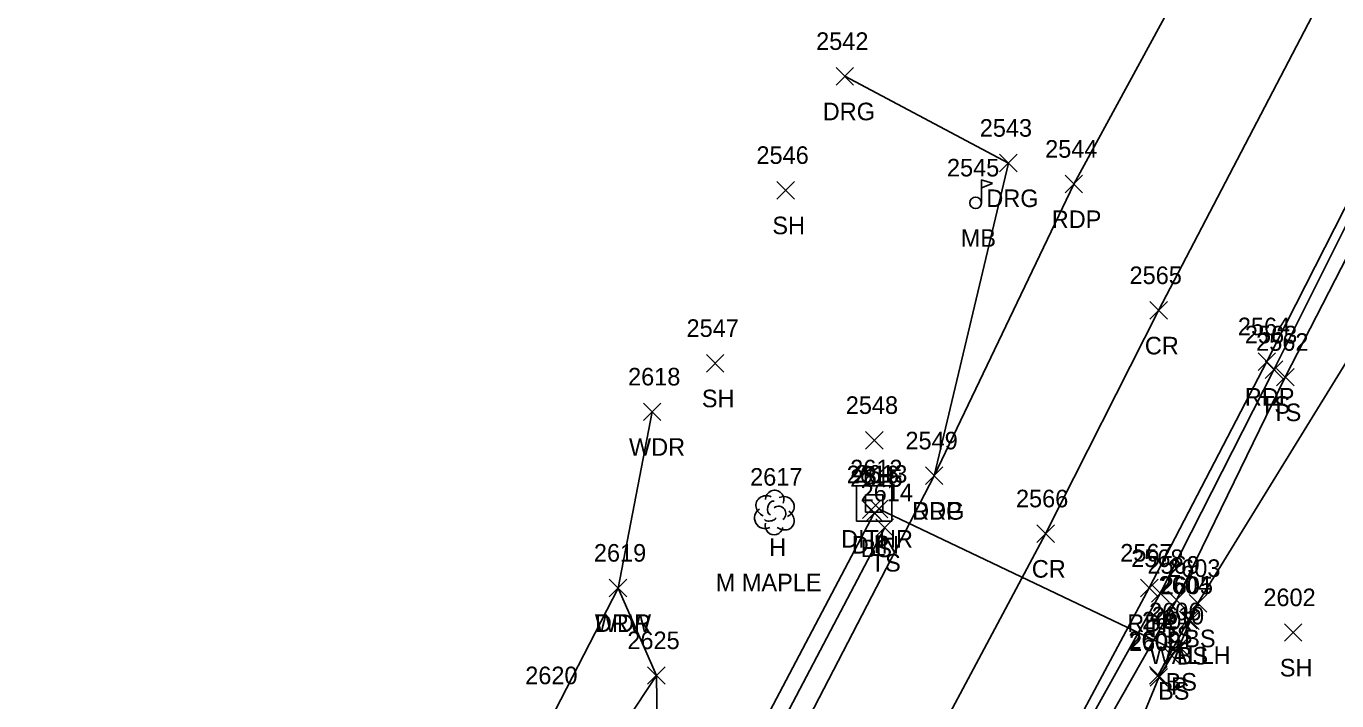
# Model space of a CAD drawing. Extents: x 1678863 to 1683592, y 407783 to 418211.
# Drawn here: x 1680535.7 to 1680684.8, y 415624 to 415700.7 of the extents above; entities that cross this region are included whole.
import ezdxf

# ---------------------------------------------------------------- set-up
doc = ezdxf.new("R2010")
doc.units = 0
for name, color, linetype in [('D_A', 7, 'Continuous'), ('D_I', 7, 'Continuous'), ('D_TIC', 7, 'Continuous'), ('DCP', 7, 'Continuous'), ('DHW', 7, 'Continuous'), ('DS', 7, 'Continuous'), ('L_A', 7, 'Continuous'), ('L_C', 7, 'Continuous'), ('L_I', 7, 'Continuous'), ('L_TIC', 7, 'Continuous'), ('LAWA', 7, 'Continuous'), ('LELB', 7, 'Continuous'), ('LMB', 7, 'Continuous'), ('LTD', 7, 'Continuous'), ('P_A', 7, 'Continuous'), ('P_I', 7, 'Continuous'), ('P_TIC', 7, 'Continuous'), ('PET', 7, 'Continuous'), ('PRC', 7, 'Continuous'), ('R_A', 7, 'Continuous'), ('R_I', 7, 'Continuous'), ('R_TIC', 7, 'Continuous'), ('RDG', 7, 'Continuous'), ('RDW', 7, 'Continuous')]:
    doc.layers.add(name, color=color, linetype=linetype)

msp = doc.modelspace()

# ---------------------------------------------------------------- linework, layer by layer
at = {"layer": 'D_TIC'}
for points in [[(1680630.83, 415644.77), (1680632.83, 415646.77)], [(1680632.83, 415644.77), (1680630.83, 415646.77)], [(1680631.72, 415644.83), (1680633.72, 415646.83)], [(1680633.72, 415644.83), (1680631.72, 415646.83)], [(1680666.89, 415632.2), (1680668.89, 415634.2)], [(1680668.89, 415632.2), (1680666.89, 415634.2)], [(1680665.55, 415628.71), (1680667.55, 415630.71)], [(1680667.55, 415628.71), (1680665.55, 415630.71)], [(1680663.46, 415625.93), (1680665.46, 415627.93)], [(1680665.46, 415625.93), (1680663.46, 415627.93)]]:
    msp.add_lwpolyline(points, dxfattribs=at)
at = {"layer": 'DCP'}
msp.add_lwpolyline([(1680666.55, 415629.71), (1680632.72, 415645.83)], dxfattribs=at)
at = {"layer": 'DHW'}
msp.add_lwpolyline([(1680667.89, 415633.2), (1680664.46, 415626.93)], dxfattribs=at)
at = {"layer": 'DS'}
for p, q in [((1680630.15, 415648.46), (1680634.15, 415648.46)), ((1680630.15, 415644.46), (1680630.16, 415648.46)), ((1680631.15, 415647.46), (1680633.15, 415647.46)), ((1680631.15, 415645.46), (1680631.15, 415647.46)), ((1680633.15, 415647.46), (1680633.15, 415645.46)), ((1680634.15, 415648.46), (1680634.15, 415644.46)), ((1680632.15, 415646.47), (1680632.15, 415646.47)), ((1680633.15, 415645.46), (1680631.15, 415645.46)), ((1680634.15, 415644.46), (1680630.15, 415644.46)), ((1680632.65, 415644.46), (1680633.15, 415644.46))]:
    msp.add_line(p, q, dxfattribs=at)
at = {"layer": 'L_TIC'}
for points in [[(1680621.08, 415681.09), (1680623.08, 415683.09)], [(1680623.08, 415681.09), (1680621.08, 415683.09)], [(1680613.07, 415661.41), (1680615.07, 415663.41)], [(1680615.07, 415661.41), (1680613.07, 415663.41)], [(1680676.63, 415660.68), (1680678.63, 415662.68)], [(1680678.63, 415660.68), (1680676.63, 415662.68)], [(1680677.91, 415659.83), (1680679.91, 415661.83)], [(1680679.91, 415659.83), (1680677.91, 415661.83)], [(1680605.9, 415655.89), (1680607.9, 415657.89)], [(1680607.9, 415655.89), (1680605.9, 415657.89)], [(1680631.18, 415652.65), (1680633.18, 415654.65)], [(1680633.18, 415652.65), (1680631.18, 415654.65)], [(1680631.17, 415644.36), (1680633.17, 415646.36)], [(1680633.17, 415644.36), (1680631.17, 415646.36)], [(1680632.35, 415642.72), (1680634.35, 415644.72)], [(1680634.35, 415642.72), (1680632.35, 415644.72)], [(1680602.02, 415635.85), (1680604.02, 415637.85)], [(1680604.02, 415635.85), (1680602.02, 415637.85)], [(1680663.7, 415635.24), (1680665.7, 415637.24)], [(1680665.7, 415635.24), (1680663.7, 415637.24)], [(1680665.54, 415634.48), (1680667.54, 415636.48)], [(1680667.54, 415634.48), (1680665.54, 415636.48)], [(1680667.98, 415634.11), (1680669.98, 415636.11)], [(1680669.98, 415634.11), (1680667.98, 415636.11)], [(1680667.13, 415632.15), (1680669.13, 415634.15)], [(1680669.13, 415632.15), (1680667.13, 415634.15)], [(1680678.81, 415630.79), (1680680.81, 415632.79)], [(1680680.81, 415630.79), (1680678.81, 415632.79)], [(1680665.86, 415629.18), (1680667.86, 415631.18)], [(1680667.86, 415629.18), (1680665.86, 415631.18)], [(1680665.01, 415628.15), (1680667.01, 415630.15)], [(1680667.01, 415628.15), (1680665.01, 415630.15)], [(1680606.38, 415625.9), (1680608.38, 415627.9)], [(1680608.38, 415625.9), (1680606.38, 415627.9)], [(1680663.53, 415625.69), (1680665.53, 415627.69)], [(1680665.53, 415625.69), (1680663.53, 415627.69)]]:
    msp.add_lwpolyline(points, dxfattribs=at)
at = {"layer": 'LAWA'}
msp.add_lwpolyline([(1680606.9, 415656.89), (1680603.02, 415636.85), (1680607.38, 415626.9), (1680607.52, 415618.11), (1680596.78, 415583.99), (1680577.19, 415543.55), (1680564.61, 415514.54), (1680555.67, 415493.69), (1680550.62, 415482.36), (1680543.43, 415462.07), (1680536.67, 415456.94)], dxfattribs=at)
at = {"layer": 'LELB'}
for points in [[(1680779.02, 415827.07), (1680764.6, 415800.72), (1680749.76, 415782.11), (1680734.08, 415752.62), (1680721.13, 415730.53), (1680704.81, 415692.99), (1680704.75, 415688.18), (1680689.04, 415667.71), (1680668.98, 415635.11), (1680668.13, 415633.15), (1680666.86, 415630.18), (1680666.01, 415629.15), (1680664.53, 415626.69), (1680656.16, 415606.33), (1680642.64, 415571.64), (1680625.84, 415544.48), (1680606.01, 415498.25), (1680595.98, 415466.06), (1680584.22, 415440)], [(1680760.46, 415817.8), (1680759.2, 415806.58), (1680737.44, 415772.53), (1680718.55, 415734.23), (1680698.03, 415698.1), (1680678.91, 415660.83), (1680666.54, 415635.48), (1680651.21, 415608.56), (1680637.64, 415579.7), (1680620.72, 415545.75), (1680603.88, 415511.3), (1680588.55, 415474.85)], [(1680716.45, 415735.15), (1680696.34, 415699.12), (1680677.63, 415661.68), (1680664.7, 415636.24), (1680649.94, 415609.72), (1680635.85, 415580.47), (1680619.12, 415546.83), (1680602.77, 415511.81), (1680588.55, 415474.85)], [(1680632.17, 415645.36), (1680615.45, 415613.7), (1680599.55, 415582.66), (1680582, 415541.28), (1680567.86, 415513.08), (1680554.53, 415480.69), (1680546.59, 415460.78), (1680542.6, 415453.6), (1680540.64, 415455.07)], [(1680633.35, 415643.72), (1680617.1, 415612.79), (1680602.64, 415581.48), (1680583.69, 415540.74), (1680570.36, 415512.19), (1680555.93, 415479.46), (1680544.79, 415450.21), (1680534.43, 415426.53), (1680521.07, 415388.59), (1680509.57, 415354.33), (1680496.9, 415318.18), (1680492.8, 415319.1)]]:
    msp.add_lwpolyline(points, dxfattribs=at)
at = {"layer": 'LMB'}
for p, q in [((1680644.34, 415683.26), (1680645.63, 415682.88)), ((1680644.35, 415680.67), (1680644.35, 415683.26)), ((1680644.35, 415682.36), (1680645.63, 415682.87)), ((1680643.69, 415680.66), (1680643.69, 415680.66))]:
    msp.add_line(p, q, dxfattribs=at)
msp.add_circle((1680643.69, 415680.66), 0.656, dxfattribs=at)
at = {"layer": 'LTD'}
msp.add_line((1680620.78, 415645.49), (1680620.78, 415645.49), dxfattribs=at)
msp.add_line((1680620.78, 415645.49), (1680620.78, 415645.49), dxfattribs=at)
msp.add_arc((1680620.83, 415646.92), 1.05, 335.5272, 180.9563, dxfattribs=at)
for centre, major_axis, ratio, start_param, end_param in [((1680619.99, 415646.15), (1.21, -0.51), 0.895232, 1.570796, 4.712389), ((1680620.57, 415645.95), (-0.208, -0.792), 0.645439, 3.141593, 6.283185), ((1680621.28, 415645.32), (-0.5, 0.667), 0.989748, 3.141593, 6.283185), ((1680621.82, 415646.07), (-1.14, -0.48), 0.949671, 1.570796, 4.712389), ((1680619.7, 415644.78), (0.58, -1.04), 0.959034, 3.141593, 6.283185), ((1680620.32, 415644.74), (-0.625, -0.083), 0.423636, 0, 3.141593), ((1680621.78, 415644.66), (-1.09, 0.79), 0.841452, 1.570796, 4.712389), ((1680620.78, 415643.99), (0.26, 1.06), 0.942809, 1.570796, 4.712389)]:
    msp.add_ellipse(centre, major_axis=major_axis, ratio=ratio, start_param=start_param, end_param=end_param, dxfattribs=at)
at = {"layer": 'P_TIC'}
for points in [[(1680653.86, 415681.79), (1680655.86, 415683.79)], [(1680655.86, 415681.79), (1680653.86, 415683.79)], [(1680663.5, 415667.42), (1680665.5, 415669.42)], [(1680665.5, 415667.42), (1680663.5, 415669.42)], [(1680675.82, 415661.6), (1680677.82, 415663.6)], [(1680677.82, 415661.6), (1680675.82, 415663.6)], [(1680637.98, 415648.62), (1680639.98, 415650.62)], [(1680639.98, 415648.62), (1680637.98, 415650.62)], [(1680650.65, 415642.03), (1680652.65, 415644.03)], [(1680652.65, 415642.03), (1680650.65, 415644.03)], [(1680662.45, 415635.86), (1680664.45, 415637.86)], [(1680664.45, 415635.86), (1680662.45, 415637.86)]]:
    msp.add_lwpolyline(points, dxfattribs=at)
at = {"layer": 'PET'}
for points in [[(1680714.62, 415736.11), (1680695.56, 415699.43), (1680676.82, 415662.6), (1680663.45, 415636.86), (1680649.23, 415610.25), (1680634.13, 415580.72), (1680618.24, 415547.61), (1680602.16, 415512.05), (1680586.29, 415476.01), (1680574.61, 415447.7), (1680563.89, 415420.31), (1680552.33, 415389.01), (1680543.5, 415364.71), (1680535.14, 415340.61), (1680523.39, 415305.41), (1680517.77, 415286.76), (1680506.72, 415249.99), (1680495.8, 415211.55), (1680487.74, 415180.8)], [(1680674.8, 415719.5), (1680654.86, 415682.79), (1680638.98, 415649.62), (1680619.32, 415611.68), (1680604.15, 415580.83), (1680584.73, 415539.97), (1680571.82, 415511.9), (1680557.49, 415478.39), (1680544.08, 415445.87), (1680536.29, 415425.79), (1680523.06, 415388.11), (1680510.43, 415353.62), (1680497.85, 415315.66), (1680486.4, 415279.22), (1680483.29, 415266.82), (1680478.84, 415252.28), (1680468.22, 415214.69), (1680459.71, 415182.46)]]:
    msp.add_lwpolyline(points, dxfattribs=at)
at = {"layer": 'PRC'}
msp.add_lwpolyline([(1680684.22, 415706.23), (1680664.5, 415668.42), (1680651.65, 415643.03), (1680631.65, 415605.57), (1680617, 415575.83), (1680596.48, 415533.87), (1680584.46, 415507.14), (1680569.15, 415472.46), (1680556.96, 415440.74), (1680549.08, 415420.65), (1680536.22, 415384.73), (1680523.38, 415348.31), (1680512.19, 415314.3), (1680500.03, 415274.9), (1680490.66, 415243.58), (1680481.59, 415211.17), (1680473.06, 415178.67)], dxfattribs=at)
at = {"layer": 'R_TIC'}
for points in [[(1680627.81, 415694.05), (1680629.81, 415696.05)], [(1680629.81, 415694.05), (1680627.81, 415696.05)], [(1680646.42, 415684.18), (1680648.42, 415686.18)], [(1680648.42, 415684.18), (1680646.42, 415686.18)], [(1680637.98, 415648.62), (1680639.98, 415650.62)], [(1680639.98, 415648.62), (1680637.98, 415650.62)], [(1680602.02, 415635.85), (1680604.02, 415637.85)], [(1680604.02, 415635.85), (1680602.02, 415637.85)], [(1680606.38, 415625.9), (1680608.38, 415627.9)], [(1680608.38, 415625.9), (1680606.38, 415627.9)]]:
    msp.add_lwpolyline(points, dxfattribs=at)
at = {"layer": 'RDG'}
msp.add_lwpolyline([(1680628.81, 415695.05), (1680647.42, 415685.18), (1680638.98, 415649.62)], dxfattribs=at)
at = {"layer": 'RDW'}
for points in [[(1680603.02, 415636.85), (1680595.85, 415622.91), (1680580.1, 415606.3)], [(1680579.57, 415593.72), (1680597.2, 415611.55), (1680607.38, 415626.9)]]:
    msp.add_lwpolyline(points, dxfattribs=at)

# ---------------------------------------------------------------- texts
at = {"layer": 'D_A'}
for s, p in [('DITHR', (1680628.39, 415641.44)), ('DIIN', (1680629.6, 415640.77)), ('P', (1680632.1, 415640.83)), ('WALLH', (1680663.48, 415628.2)), ('P', (1680665.93, 415624.71))]:
    msp.add_text(s, height=2, dxfattribs=at).set_placement(p)
at = {"layer": 'D_I'}
for s, p in [('2616', (1680629.03, 415648.77)), ('2612', (1680629.42, 415649.44)), ('2613', (1680629.98, 415648.83)), ('2604', (1680664.5, 415636.2)), ('2610', (1680663.73, 415632.71)), ('2609', (1680661.07, 415629.93))]:
    msp.add_text(s, height=2, dxfattribs=at).set_placement(p)
at = {"layer": 'L_A'}
for s, p in [('SH', (1680620.57, 415677.09)), ('MB', (1680642, 415675.66)), ('SH', (1680612.55, 415657.41)), ('TS', (1680676.04, 415656.68)), ('TS', (1680677.32, 415655.83)), ('WDR', (1680604.26, 415651.89)), ('SH', (1680630.67, 415648.65)), ('H', (1680620.21, 415640.49)), ('BS', (1680630.61, 415640.36)), ('TS', (1680631.76, 415638.72)), ('WDR', (1680600.38, 415631.85)), ('TS', (1680663.11, 415631.24)), ('TS', (1680664.95, 415630.48)), ('BS', (1680667.42, 415630.11)), ('BS', (1680666.57, 415628.15)), ('SH', (1680678.29, 415626.79)), ('BS', (1680665.3, 415625.18)), ('BS', (1680664.45, 415624.15))]:
    msp.add_text(s, height=2, dxfattribs=at).set_placement(p)
at = {"layer": 'L_C'}
msp.add_text('M MAPLE', height=2, dxfattribs=at).set_placement((1680614.13, 415636.49))
at = {"layer": 'L_I'}
for s, p in [('2546', (1680618.76, 415685.09)), ('2545', (1680640.43, 415683.66)), ('2547', (1680610.81, 415665.41)), ('2563', (1680674.32, 415664.68)), ('2562', (1680675.6, 415663.83)), ('2618', (1680604.16, 415659.89)), ('2548', (1680628.92, 415656.65)), ('2617', (1680618.04, 415648.49)), ('2615', (1680629.43, 415648.36)), ('2614', (1680630.61, 415646.72)), ('2619', (1680600.27, 415639.85)), ('2568', (1680661.39, 415639.24)), ('2569', (1680663.23, 415638.48)), ('2603', (1680665.59, 415638.11)), ('2605', (1680664.74, 415636.15)), ('2602', (1680676.42, 415634.79)), ('2607', (1680662.62, 415632.15)), ('2606', (1680663.42, 415633.18)), ('2625', (1680604.08, 415629.9)), ('2608', (1680661.14, 415629.69))]:
    msp.add_text(s, height=2, dxfattribs=at).set_placement(p)
at = {"layer": 'P_A'}
for s, p in [('RDP', (1680652.35, 415677.79)), ('CR', (1680662.94, 415663.42)), ('RDP', (1680674.31, 415657.6)), ('RDP', (1680636.47, 415644.62)), ('CR', (1680650.08, 415638.03)), ('RDP', (1680660.94, 415631.86))]:
    msp.add_text(s, height=2, dxfattribs=at).set_placement(p)
at = {"layer": 'P_I'}
for s, p in [('2544', (1680651.6, 415685.79)), ('2565', (1680661.2, 415671.42)), ('2564', (1680673.52, 415665.6)), ('2549', (1680635.71, 415652.62)), ('2566', (1680648.28, 415646.03)), ('2567', (1680660.14, 415639.86))]:
    msp.add_text(s, height=2, dxfattribs=at).set_placement(p)
at = {"layer": 'R_A'}
for s, p in [('DRG', (1680626.3, 415690.05)), ('DRG', (1680644.91, 415680.18)), ('DRG', (1680636.47, 415644.62)), ('DRW', (1680600.39, 415631.85))]:
    msp.add_text(s, height=2, dxfattribs=at).set_placement(p)
at = {"layer": 'R_I'}
for s, p in [('2542', (1680625.55, 415698.05)), ('2543', (1680644.16, 415688.18)), ('2549', (1680635.71, 415652.62)), ('2619', (1680600.27, 415639.85)), ('2625', (1680604.08, 415629.9)), ('2620', (1680592.46, 415625.91))]:
    msp.add_text(s, height=2, dxfattribs=at).set_placement(p)

doc.saveas('drawing.dxf')
